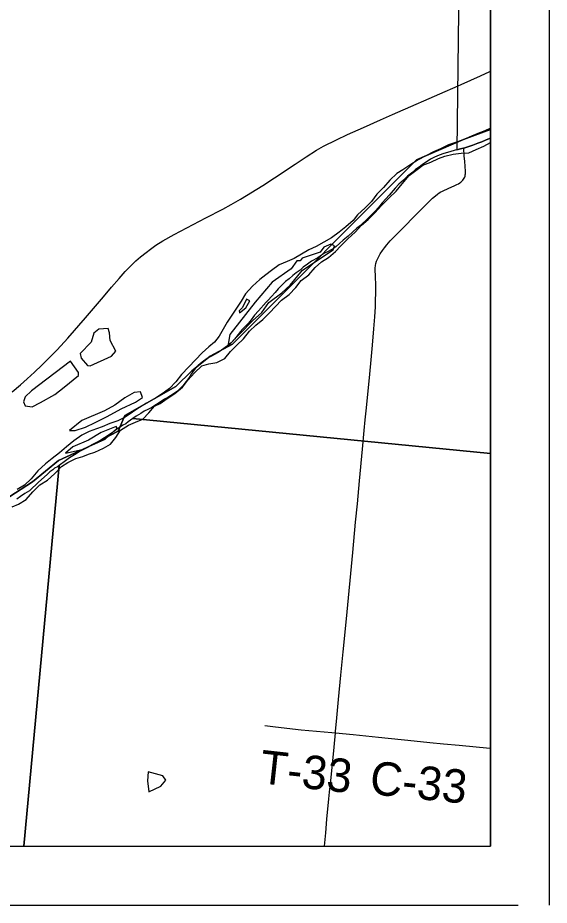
# Model space of a CAD drawing. Extents: x -784 to 1375, y -225 to 440.
# Drawn here: x 564.18 to 582.24, y 281.31 to 311.43 of the extents above; entities that cross this region are included whole.
import ezdxf

# ---------------------------------------------------------------- set-up
doc = ezdxf.new("R2010")
doc.units = 0
for name, color, linetype in [('GM_X_County_Road', 7, 'Continuous'), ('GM_X_County_Road_Text', 7, 'Continuous'), ('GM_X_Major_River', 7, 'Continuous'), ('GM_X_Minor_Lake', 7, 'Continuous'), ('GM_X_Section', 7, 'Continuous'), ('GM_X_State_Route', 7, 'Continuous'), ('GM_X_Township', 7, 'Continuous'), ('GM_X_Township_Road', 7, 'Continuous'), ('GM_X_Township_Road_Text', 7, 'Continuous'), ('SH_Data', 7, 'Continuous')]:
    doc.layers.add(name, color=color, linetype=linetype)

msp = doc.modelspace()

# ---------------------------------------------------------------- linework, layer by layer
at = {"layer": 'GM_X_County_Road'}
for points in [[(574.976, 287.155), (574.98, 287.202), (575.024, 287.672), (575.078, 288.291), (575.157, 289.12), (575.237, 289.911), (575.344, 291.025), (575.56, 293.276), (575.658, 294.315), (575.719, 294.933), (575.79, 295.713), (575.888, 296.79), (575.947, 297.422), (575.979, 297.78), (576.013, 298.088), (576.115, 299.102), (576.174, 299.695), (576.232, 300.314), (576.283, 300.871), (576.315, 301.276), (576.329, 301.62), (576.341, 302.311), (576.33, 302.694), (576.325, 302.837), (576.325, 302.937), (576.335, 303.024), (576.35, 303.096), (576.371, 303.164), (576.404, 303.239), (576.447, 303.333), (576.496, 303.414), (576.568, 303.527), (576.641, 303.626), (576.719, 303.721), (576.834, 303.856), (577.107, 304.128), (577.334, 304.357), (577.628, 304.661), (577.891, 304.939), (578.273, 305.311), (578.369, 305.391), (578.439, 305.444), (578.502, 305.486), (578.556, 305.518), (578.609, 305.547), (578.678, 305.583), (578.752, 305.616), (578.826, 305.649), (579.01, 305.725), (579.098, 305.767), (579.15, 305.797), (579.194, 305.827), (579.227, 305.85), (579.258, 305.874), (579.297, 305.915), (579.327, 305.958), (579.348, 305.989), (579.363, 306.019), (579.375, 306.055), (579.384, 306.095), (579.391, 306.137), (579.394, 306.18), (579.394, 306.218), (579.381, 306.389), (579.366, 306.558), (579.349, 306.749), (579.329, 306.989)], [(574.602, 283.309), (574.644, 283.765), (574.686, 284.234), (574.75, 284.915), (574.775, 285.15), (574.814, 285.533), (574.928, 286.67), (574.976, 287.155)], [(574.976, 287.155), (575.571, 287.099), (576.436, 287.01), (577.648, 286.891), (578.179, 286.836), (578.649, 286.792), (579.181, 286.74), (580.22, 286.642), (580.236, 286.641)]]:
    msp.add_lwpolyline(points, dxfattribs=at)
at = {"layer": 'GM_X_Major_River'}
for p, q in [((571.704, 301.482), (571.71, 301.414)), ((567.564, 297.504), (567.528, 297.558))]:
    msp.add_line(p, q, dxfattribs=at)
for points in [[(580.236, 307.681), (580.053, 307.592), (579.808, 307.507), (579.592, 307.414), (579.338, 307.298), (579.085, 307.213), (578.816, 307.121), (578.546, 306.983), (578.3, 306.883), (578.038, 306.745), (577.784, 306.606), (577.505, 306.431), (577.258, 306.269), (577.064, 306.145), (576.823, 305.915), (576.611, 305.669), (576.384, 305.439), (576.203, 305.199), (575.985, 304.984), (575.728, 304.739), (575.578, 304.545), (575.322, 304.338), (575.096, 304.154), (574.841, 303.962), (574.316, 303.671), (574.069, 303.555), (573.575, 303.263), (573.329, 303.155), (573.067, 303.04), (572.804, 302.848), (572.61, 302.701), (572.408, 302.546), (572.159, 302.316), (571.924, 302.063), (571.773, 301.808), (571.615, 301.576), (571.299, 301.096), (571.156, 300.856), (571.021, 300.624), (570.871, 300.422), (570.669, 300.267), (570.444, 300.059), (570.224, 299.821), (569.99, 299.583), (569.74, 299.323), (569.552, 299.076), (569.333, 298.845), (569.092, 298.669), (568.83, 298.5), (568.559, 298.347), (568.32, 298.208), (568.08, 298.047), (567.832, 297.878), (567.578, 297.747), (567.31, 297.655), (567.056, 297.547), (566.856, 297.476), (566.61, 297.383), (566.356, 297.26), (566.085, 297.068)], [(567.33, 296.961), (567.519, 297.185), (567.677, 297.432), (567.947, 297.601), (568.186, 297.701), (568.432, 297.809), (568.635, 298.017), (568.823, 298.249), (569.016, 298.335), (569.256, 298.512), (569.519, 298.681), (569.775, 298.888), (569.964, 299.127), (570.191, 299.38), (570.432, 299.618), (570.678, 299.688), (570.945, 299.727), (571.222, 299.864), (571.411, 300.103), (571.629, 300.319), (571.855, 300.534), (572.052, 300.796), (572.27, 300.996), (572.511, 301.195), (572.737, 301.418), (572.933, 301.634), (573.144, 301.842), (573.407, 302.033), (573.626, 302.279), (573.807, 302.511), (574.071, 302.71), (574.29, 302.955), (574.501, 303.148), (574.74, 303.294), (574.973, 303.494), (575.153, 303.695), (575.395, 303.925), (575.644, 304.155), (575.863, 304.386), (576.089, 304.586), (576.308, 304.808), (576.542, 305.061), (576.8, 305.322), (577.041, 305.544), (577.238, 305.79), (577.481, 306.073), (577.745, 306.28), (577.946, 306.427), (578.208, 306.527), (578.477, 306.657), (578.692, 306.736), (578.976, 306.805), (579.243, 306.836), (579.509, 306.852), (579.748, 306.96), (580.01, 307.076), (580.236, 307.201)], [(574.94, 303.685), (574.812, 303.742), (574.574, 303.641), (574.456, 303.477), (573.849, 303.271), (573.771, 303.182), (573.664, 303.177), (573.467, 302.908), (572.824, 302.452), (572.252, 301.781), (571.387, 300.683), (571.314, 300.289)], [(571.314, 300.289), (572.16, 301.143), (572.479, 301.432), (572.708, 301.762), (573.158, 302.093), (573.438, 302.352), (573.854, 302.86), (574.891, 303.557), (574.94, 303.685)], [(572.064, 301.826), (571.95, 301.88), (571.814, 301.601), (571.704, 301.482)], [(571.71, 301.414), (571.935, 301.583), (572.064, 301.826)], [(567.528, 297.558), (567.013, 297.35), (566.588, 297.094), (566.057, 296.863), (565.801, 296.654)], [(565.801, 296.654), (566.375, 296.772), (567.152, 297.133), (567.564, 297.504)], [(566.085, 297.068), (565.837, 296.869), (565.603, 296.669), (565.355, 296.47), (565.122, 296.293), (564.865, 296.055), (564.638, 295.787), (564.412, 295.571), (564.165, 295.418)], [(563.99, 294.828), (564.206, 294.921), (564.468, 295.075), (564.695, 295.336), (564.937, 295.573), (565.192, 295.742), (565.433, 295.95), (565.675, 296.195), (565.884, 296.334), (566.162, 296.472), (566.392, 296.543), (566.584, 296.622), (566.806, 296.692), (567.091, 296.822), (567.33, 296.961)]]:
    msp.add_lwpolyline(points, dxfattribs=at)
at = {"layer": 'GM_X_Minor_Lake'}
msp.add_line((564.651, 298.766), (564.433, 298.565), dxfattribs=at)
for points in [[(567.511, 300.118), (567.326, 300.473), (567.303, 300.74), (567.253, 300.879), (566.933, 300.864), (566.77, 300.731), (566.678, 300.421), (566.302, 300.033)], [(566.302, 300.033), (566.338, 299.881), (566.552, 299.632), (566.643, 299.622), (567.367, 299.946), (567.511, 300.118)], [(564.433, 298.565), (564.376, 298.392), (564.441, 298.26), (564.676, 298.224), (564.961, 298.369), (565.447, 298.639), (565.758, 298.89), (566.247, 299.289), (566.242, 299.388), (565.977, 299.776), (564.651, 298.766)], [(565.936, 297.423), (566.132, 297.418), (566.485, 297.531), (566.808, 297.69), (567.217, 297.901), (567.695, 298.163), (568.18, 298.387), (568.42, 298.541), (568.357, 298.733)], [(568.357, 298.733), (568.142, 298.716), (567.826, 298.533), (567.485, 298.283), (567.13, 298.094), (566.361, 297.762), (565.936, 297.423)], [(568.611, 285.842), (568.593, 285.535), (568.631, 285.161)], [(568.631, 285.161), (569.045, 285.348), (569.21, 285.55), (569.115, 285.705), (568.611, 285.842)]]:
    msp.add_lwpolyline(points, dxfattribs=at)
at = {"layer": 'GM_X_Section'}
for p, q in [((580.236, 307.348), (580.236, 313.496)), ((580.236, 296.639), (580.236, 307.348)), ((554.103, 283.309), (564.388, 283.309))]:
    msp.add_line(p, q, dxfattribs=at)
for points in [[(579.171, 313.507), (579.102, 306.948), (579.042, 306.942), (578.859, 306.877), (578.653, 306.82), (578.493, 306.762), (578.341, 306.704), (578.203, 306.631), (578.088, 306.557), (577.935, 306.454), (577.812, 306.365), (577.697, 306.283), (577.597, 306.194), (577.42, 306.053), (577.282, 305.92), (577.128, 305.786), (576.997, 305.652), (576.803, 305.413), (576.687, 305.286), (576.564, 305.152), (576.432, 304.987), (576.309, 304.853), (576.201, 304.741), (576.078, 304.622), (575.823, 304.384), (575.701, 304.288), (575.562, 304.162), (575.401, 304.02), (575.232, 303.887), (575.108, 303.768), (574.993, 303.672), (574.909, 303.605), (574.824, 303.553), (574.702, 303.487), (574.603, 303.443), (574.503, 303.37), (574.373, 303.288), (574.166, 303.171), (574.028, 303.067), (573.883, 302.971), (573.775, 302.867), (573.637, 302.778), (573.529, 302.682), (573.398, 302.571), (573.283, 302.474), (573.152, 302.355), (573.029, 302.236), (572.921, 302.102), (572.797, 301.967), (572.689, 301.848), (572.62, 301.773), (572.365, 301.483), (572.226, 301.333), (572.109, 301.176), (572.024, 301.064), (571.931, 300.975), (571.831, 300.878), (571.739, 300.766), (571.669, 300.677), (571.545, 300.52), (571.437, 300.4), (571.306, 300.297), (571.022, 300.089), (570.892, 300.016), (570.747, 299.935), (570.617, 299.862), (570.494, 299.78), (570.394, 299.699), (570.295, 299.617), (570.225, 299.535), (570.148, 299.453), (570.085, 299.356), (570.023, 299.258), (569.945, 299.138), (569.86, 299.034), (569.79, 298.937), (569.698, 298.847), (569.605, 298.758), (569.491, 298.677), (569.376, 298.603), (569.276, 298.544), (569.169, 298.485), (569.054, 298.411), (568.74, 298.205), (568.603, 298.139), (568.473, 298.073), (568.365, 297.999), (568.205, 297.911), (568.097, 297.83), (567.936, 297.711), (567.859, 297.652), (567.752, 297.601), (567.637, 297.519), (567.538, 297.461), (567.438, 297.379), (567.3, 297.283), (567.185, 297.202), (567.07, 297.143), (566.932, 297.054), (566.802, 296.981), (566.672, 296.908), (566.55, 296.849), (566.435, 296.79), (566.305, 296.717), (566.106, 296.599), (565.946, 296.496), (565.8, 296.392), (565.593, 296.237), (565.531, 296.193), (565.432, 296.141), (565.378, 296.089), (565.278, 296.015), (565.178, 295.926), (564.886, 295.674), (564.793, 295.577), (564.686, 295.472), (564.578, 295.376), (564.425, 295.288), (564.279, 295.184), (564.149, 295.088)], [(580.236, 313.496), (579.171, 313.507), (579.102, 306.948), (579.216, 306.977), (579.369, 307.019), (579.643, 307.106), (579.811, 307.171), (579.948, 307.222), (580.093, 307.287), (580.236, 307.348)], [(580.236, 307.348), (580.093, 307.287), (579.948, 307.222), (579.811, 307.171), (579.643, 307.106), (579.369, 307.019), (579.216, 306.977), (579.102, 306.948), (579.042, 306.942), (578.859, 306.877), (578.653, 306.82), (578.493, 306.762), (578.341, 306.704), (578.203, 306.631), (578.088, 306.557), (577.935, 306.454), (577.812, 306.365), (577.697, 306.283), (577.597, 306.194), (577.42, 306.053), (577.282, 305.92), (577.128, 305.786), (576.997, 305.652), (576.803, 305.413), (576.687, 305.286), (576.564, 305.152), (576.432, 304.987), (576.309, 304.853), (576.201, 304.741), (576.078, 304.622), (575.823, 304.384), (575.701, 304.288), (575.562, 304.162), (575.401, 304.02), (575.232, 303.887), (575.108, 303.768), (574.993, 303.672), (574.909, 303.605), (574.824, 303.553), (574.702, 303.487), (574.603, 303.443), (574.503, 303.37), (574.373, 303.288), (574.166, 303.171), (574.028, 303.067), (573.883, 302.971), (573.775, 302.867), (573.637, 302.778), (573.529, 302.682), (573.398, 302.571), (573.283, 302.474), (573.152, 302.355), (573.029, 302.236), (572.921, 302.102), (572.797, 301.967), (572.689, 301.848), (572.62, 301.773), (572.365, 301.483), (572.226, 301.333), (572.109, 301.176), (572.024, 301.064), (571.931, 300.975), (571.831, 300.878), (571.739, 300.766), (571.669, 300.677), (571.545, 300.52), (571.437, 300.4), (571.306, 300.297), (571.022, 300.089), (570.892, 300.016), (570.747, 299.935), (570.617, 299.862), (570.494, 299.78), (570.394, 299.699), (570.295, 299.617), (570.225, 299.535), (570.148, 299.453), (570.085, 299.356), (570.023, 299.258), (569.945, 299.138), (569.86, 299.034), (569.79, 298.937), (569.698, 298.847), (569.605, 298.758), (569.491, 298.677), (569.376, 298.603), (569.276, 298.544), (569.169, 298.485), (569.054, 298.411), (568.74, 298.205), (568.603, 298.139), (568.473, 298.073), (568.365, 297.999), (568.205, 297.911), (568.097, 297.83), (580.236, 296.639)], [(580.236, 296.639), (568.097, 297.83), (567.936, 297.711), (567.859, 297.652), (567.752, 297.601), (567.637, 297.519), (567.538, 297.461), (567.438, 297.379), (567.3, 297.283), (567.185, 297.202), (567.07, 297.143), (566.932, 297.054), (566.802, 296.981), (566.672, 296.908), (566.55, 296.849), (566.435, 296.79), (566.305, 296.717), (566.106, 296.599), (565.946, 296.496), (565.8, 296.392), (565.593, 296.237), (564.388, 283.309)], [(564.388, 283.309), (580.236, 283.309), (580.236, 296.639)], [(564.388, 283.309), (565.593, 296.237), (565.531, 296.193), (565.432, 296.141), (565.378, 296.089), (565.278, 296.015), (565.178, 295.926), (564.886, 295.674), (564.793, 295.577), (564.686, 295.472), (564.578, 295.376), (564.425, 295.288), (564.279, 295.184), (564.149, 295.088)]]:
    msp.add_lwpolyline(points, dxfattribs=at)
at = {"layer": 'GM_X_State_Route'}
for points in [[(575.384, 307.464), (575.927, 307.706), (576.506, 307.965), (576.914, 308.145), (577.72, 308.5), (577.976, 308.611), (578.517, 308.85), (579.142, 309.126), (579.242, 309.171), (579.898, 309.465), (580.221, 309.606), (580.236, 309.613)], [(563.991, 298.739), (564.277, 298.976), (564.502, 299.171), (564.75, 299.397), (565.001, 299.636), (565.23, 299.864), (565.517, 300.157), (565.887, 300.559), (566.485, 301.241), (567.1, 301.957), (567.37, 302.282), (567.628, 302.585), (567.836, 302.817), (568.018, 303.005), (568.197, 303.179), (568.356, 303.319), (568.54, 303.469), (568.69, 303.58), (568.874, 303.708), (569.116, 303.863), (569.499, 304.07), (570.577, 304.637), (571.148, 304.94), (571.43, 305.096), (571.744, 305.273), (572.507, 305.739), (572.901, 305.998), (573.604, 306.467), (573.977, 306.714), (574.325, 306.933), (574.563, 307.068), (575.009, 307.291), (575.384, 307.464)]]:
    msp.add_lwpolyline(points, dxfattribs=at)
at = {"layer": 'GM_X_Township'}
for points in [[(563.718, 295.062), (564.688, 295.684), (565.563, 296.401), (566.526, 296.848), (567.593, 297.394), (567.816, 297.931), (569.558, 298.916), (570.094, 299.453), (570.719, 299.945), (571.479, 300.348), (577.731, 306.611), (579.324, 307.294), (580.236, 307.641), (580.236, 381.078)], [(554.071, 283.309), (580.236, 283.309), (580.236, 307.641)], [(580.236, 307.641), (579.324, 307.294), (577.731, 306.611), (571.479, 300.348), (570.719, 299.945), (570.094, 299.453), (569.558, 298.916), (567.816, 297.931), (567.593, 297.394), (566.526, 296.848), (565.563, 296.401), (564.688, 295.684), (563.718, 295.062)]]:
    msp.add_lwpolyline(points, dxfattribs=at)
at = {"layer": 'GM_X_Township_Road'}
msp.add_lwpolyline([(572.575, 287.404), (572.933, 287.363), (573.809, 287.264), (574.849, 287.167), (574.976, 287.155)], dxfattribs=at)
at = {"layer": 'SH_Data'}
for p, q in [((582.236, 421.309), (582.236, 281.309)), ((580.236, 419.309), (580.236, 283.309)), ((444.236, 283.309), (580.236, 283.309)), ((442.236, 281.309), (581.184, 281.309))]:
    msp.add_line(p, q, dxfattribs=at)

# ---------------------------------------------------------------- texts
at = {"layer": 'GM_X_County_Road_Text'}
msp.add_text('C-33', height=1.1364, rotation=354.2003, dxfattribs=at).set_placement((576.108, 285.085))
at = {"layer": 'GM_X_Township_Road_Text'}
msp.add_text('T-33', height=1.1364, rotation=353.6978, dxfattribs=at).set_placement((572.367, 285.454))

doc.saveas('drawing.dxf')
